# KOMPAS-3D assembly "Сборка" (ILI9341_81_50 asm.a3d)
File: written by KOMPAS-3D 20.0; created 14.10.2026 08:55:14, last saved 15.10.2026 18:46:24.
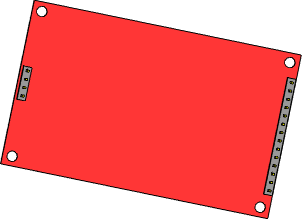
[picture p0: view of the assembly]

Document properties: Полное имя файла: D:\myProjects\Progect_esp32\box_compas\монитор\ILI9341_81_50 asm.a3d

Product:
- Part/product: Сборка
    Масса: 0.0972179
  - Component [detail]: Деталь  | Масса: 0.000521406; source file: ..\разъемы\pls_4.m3d
  - Component [detail]: Деталь  | Масса: 0.00182492; source file: ..\разъемы\pls_14.m3d
  - Component [detail]: Деталь  | Масса: 0.0948715; source file: ILI9341_81х50.m3d

Referenced files in D:\myProjects\Progect_esp32\box_compas\монитор\: ILI9341_81х50.m3d
Referenced files in D:\myProjects\Progect_esp32\box_compas\разъемы\: pls_14.m3d, pls_4.m3d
